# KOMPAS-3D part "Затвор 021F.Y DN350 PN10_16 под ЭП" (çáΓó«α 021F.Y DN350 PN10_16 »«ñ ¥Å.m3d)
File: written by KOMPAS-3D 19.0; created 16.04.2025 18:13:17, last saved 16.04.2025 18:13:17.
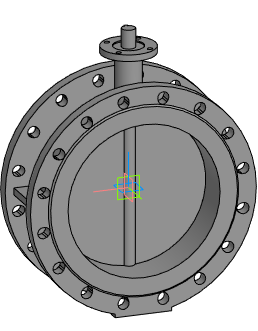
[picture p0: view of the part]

Document properties: Автор: Евгений; Полное имя файла: E:\Dendor Работа Сачек\3D для проекитирвщиков\1.6 Тип 021F.Y Затвор дисковый поворотный фланцевый\stp_Тип 021F.Y Затвор  DN40 PN10_16 под ЭП\Затвор 021F.Y DN350 PN10_16 под ЭП.m3d

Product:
- Part/product: Затвор 021F.Y DN350 PN10_16 под ЭП

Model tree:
1. Операция без истории:1  (labels: Затвор 021F.Y DN350 PN10_16 под ЭП)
